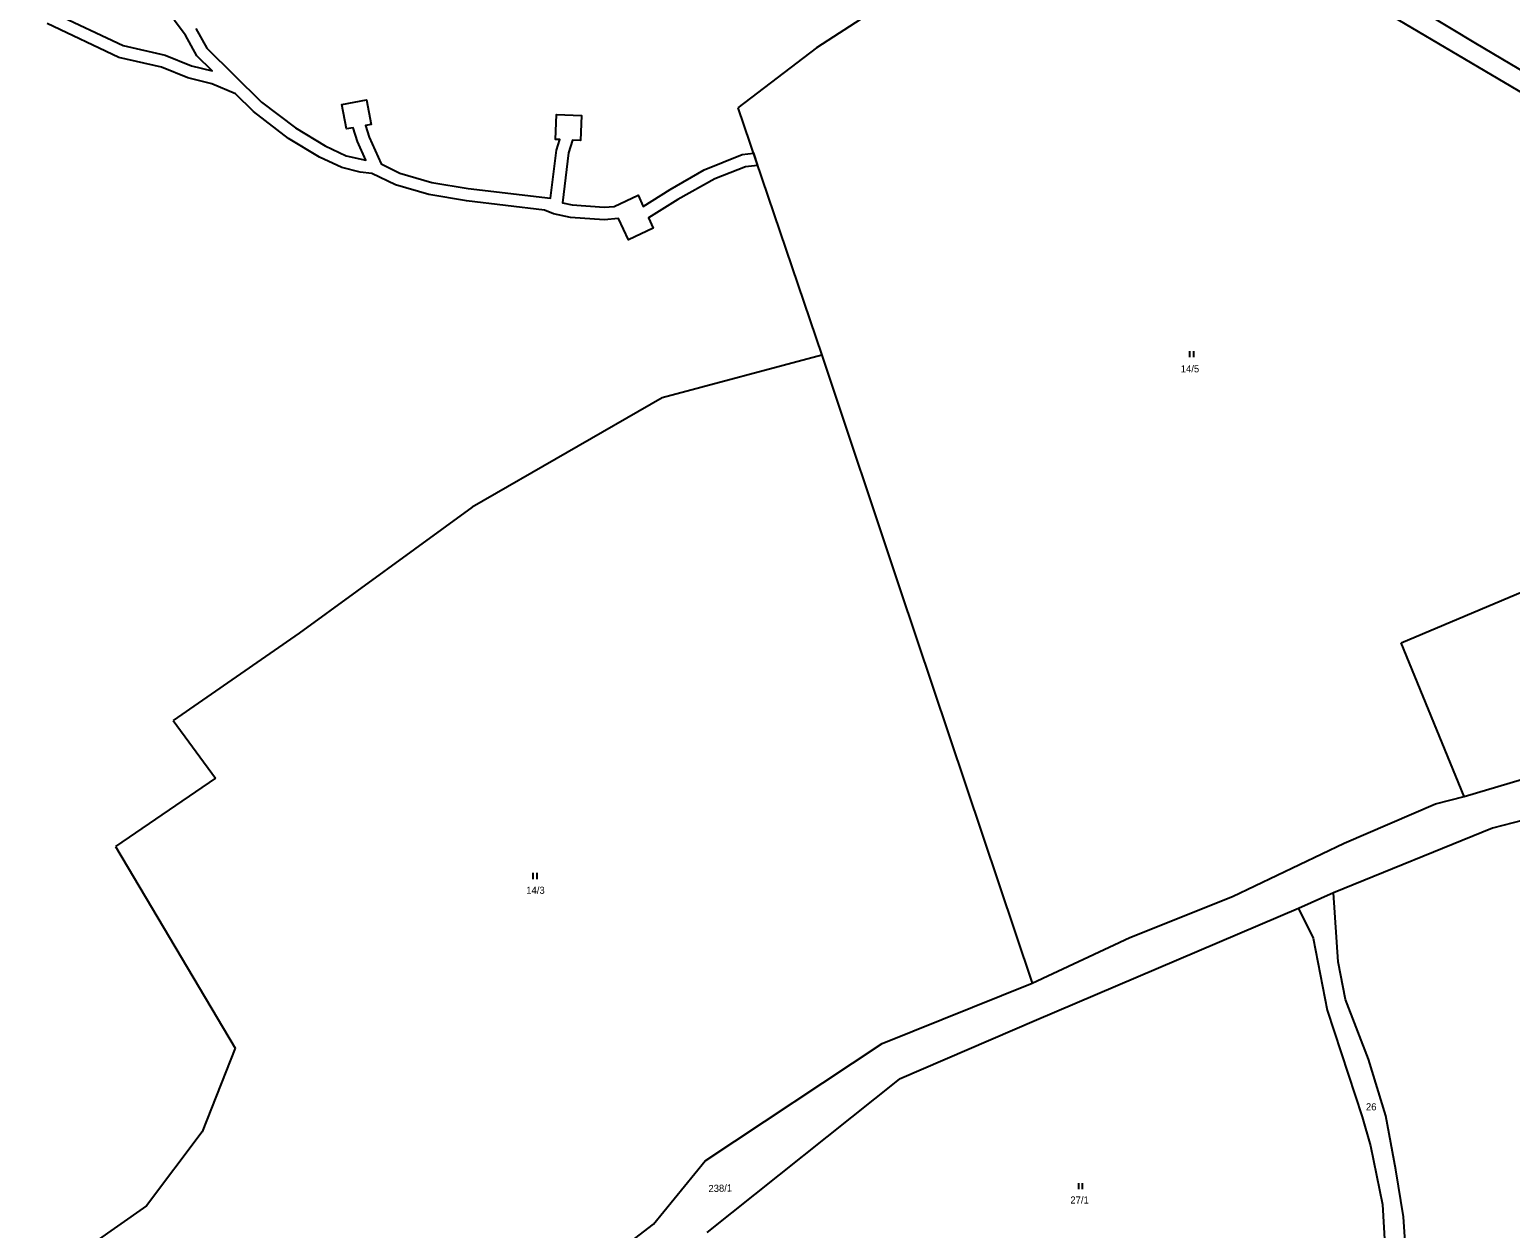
# Model space of a CAD drawing. Extents: x -811039 to -805820, y -1161436 to -1155864.
# Drawn here: x -810524 to -810168.6, y -1160756.4 to -1160468.8 of the extents above; entities that cross this region are included whole.
import ezdxf

# ---------------------------------------------------------------- set-up
doc = ezdxf.new("R2010")
doc.units = 0
for name, color, linetype in [('Default', 7, 'Continuous'), ('Hranice parcel', 7, 'Continuous'), ('Parcelní čísla', 7, 'Continuous'), ('Věcná břemena k části', 7, 'Continuous'), ('Značky kultur', 7, 'Continuous')]:
    doc.layers.add(name, color=color, linetype=linetype)

# ---------------------------------------------------------------- blocks, each defined once
blk = doc.blocks.new('306')
at = {"layer": 'Default'}
for p, q in [((-0.5, 1.5), (-0.5, 0)), ((0.5, 0), (0.5, 1.5))]:
    blk.add_line(p, q, dxfattribs=at)

msp = doc.modelspace()

# ---------------------------------------------------------------- linework, layer by layer
at = {"layer": 'Hranice parcel'}
for p, q in [((-810269.19, -1160416.44), (-810176.95, -1160472.03)), ((-810271.14, -1160421.57), (-810121.75, -1160510.04)), ((-810323.16, -1160465.39), (-810335.15, -1160473.2)), ((-810335.15, -1160473.2), (-810353.97, -1160487.55)), ((-810176.95, -1160472.03), (-810119.8, -1160505.99)), ((-810353.97, -1160487.55), (-810333.83, -1160546.92)), ((-810333.83, -1160546.92), (-810372.15, -1160557.14)), ((-810333.83, -1160546.92), (-810315.21, -1160602.74)), ((-810372.15, -1160557.14), (-810417.74, -1160583.35)), ((-810417.74, -1160583.35), (-810459.3, -1160613.56)), ((-810194.78, -1160615.88), (-810151.5, -1160597.61)), ((-810315.21, -1160602.74), (-810283.33, -1160697.52)), ((-810459.3, -1160613.56), (-810489.53, -1160634.52)), ((-810179.68, -1160652.75), (-810194.78, -1160615.88)), ((-810489.53, -1160634.52), (-810479.35, -1160648.33)), ((-810093.44, -1160639.73), (-810172.86, -1160660.38)), ((-810179.68, -1160652.75), (-810160.58, -1160647.09)), ((-810479.35, -1160648.33), (-810503.37, -1160664.79)), ((-810208.52, -1160663.94), (-810186.6, -1160654.54)), ((-810186.6, -1160654.54), (-810179.68, -1160652.75)), ((-810172.86, -1160660.38), (-810211.06, -1160675.9)), ((-810503.37, -1160664.79), (-810474.66, -1160713.13)), ((-810235.32, -1160676.73), (-810208.52, -1160663.94)), ((-810259.89, -1160686.62), (-810235.32, -1160676.73)), ((-810211.06, -1160675.9), (-810219.42, -1160679.63)), ((-810209.89, -1160692.44), (-810211.06, -1160675.9)), ((-810219.42, -1160679.63), (-810282.35, -1160706.39)), ((-810219.42, -1160679.63), (-810215.96, -1160686.74)), ((-810283.33, -1160697.52), (-810259.89, -1160686.62)), ((-810215.96, -1160686.74), (-810212.53, -1160703.99)), ((-810208.19, -1160701.46), (-810209.89, -1160692.44)), ((-810319.37, -1160712.03), (-810283.33, -1160697.52)), ((-810202.65, -1160715.73), (-810208.19, -1160701.46)), ((-810212.53, -1160703.99), (-810204.21, -1160729.61)), ((-810282.35, -1160706.39), (-810315.18, -1160720.58)), ((-810361.85, -1160740.15), (-810319.37, -1160712.03)), ((-810474.66, -1160713.13), (-810482.58, -1160733.22)), ((-810198.53, -1160729.37), (-810202.65, -1160715.73)), ((-810361.37, -1160757.38), (-810315.18, -1160720.58)), ((-810204.21, -1160729.61), (-810202.14, -1160736.58)), ((-810196.12, -1160742.31), (-810198.53, -1160729.37)), ((-810482.58, -1160733.22), (-810495.95, -1160750.93)), ((-810202.14, -1160736.58), (-810199.32, -1160750.66)), ((-810374.25, -1160755.33), (-810361.85, -1160740.15)), ((-810194.28, -1160753.55), (-810196.12, -1160742.31)), ((-810495.95, -1160750.93), (-810523.97, -1160770.58)), ((-810199.32, -1160750.66), (-810197.13, -1160787.69)), ((-810192.37, -1160781.09), (-810194.28, -1160753.55)), ((-810383.89, -1160762.81), (-810374.25, -1160755.33))]:
    msp.add_line(p, q, dxfattribs=at)
at = {"layer": 'Věcná břemena k části'}
for points in [[(-810518.54, -1160464.64), (-810501.53, -1160472.65), (-810491.43, -1160474.96), (-810485.1, -1160477.48), (-810480.15, -1160478.7), (-810483.82, -1160475.09), (-810486.58, -1160470.17), (-810489.25, -1160466.5)], [(-810484.05, -1160468.55), (-810481.41, -1160473.25), (-810468.29, -1160486.2), (-810460.13, -1160492.4), (-810453.05, -1160496.66), (-810448.01, -1160499.05), (-810443.32, -1160500.12), (-810445.29, -1160495.64), (-810446.36, -1160492.35), (-810447.9, -1160492.64), (-810449.01, -1160486.74), (-810443.11, -1160485.63), (-810442, -1160491.53), (-810443.39, -1160491.79), (-810442.48, -1160494.57), (-810439.64, -1160501.03), (-810435.09, -1160503.22), (-810427.47, -1160505.44), (-810418.71, -1160506.88), (-810398.98, -1160509.23), (-810397.56, -1160497.69), (-810396.76, -1160495.19), (-810397.78, -1160495.15), (-810397.5, -1160489.15), (-810391.51, -1160489.43), (-810391.79, -1160495.42), (-810393.66, -1160495.34), (-810394.62, -1160498.34), (-810396.1, -1160510.39), (-810393.74, -1160510.87), (-810386.08, -1160511.42), (-810383.71, -1160511.2), (-810377.93, -1160508.55), (-810376.73, -1160511.2), (-810370.23, -1160507.17), (-810362.09, -1160502.46), (-810352.93, -1160498.78), (-810350.27, -1160498.45), (-810349.28, -1160501.38), (-810352.18, -1160501.71), (-810359.5, -1160504.63), (-810368.43, -1160509.58), (-810375.48, -1160513.94), (-810374.34, -1160516.45), (-810380.21, -1160519.22), (-810382.67, -1160514.12), (-810386.05, -1160514.43), (-810394.15, -1160513.85), (-810398.21, -1160513.02), (-810400.4, -1160512.08), (-810419.13, -1160509.85), (-810428.14, -1160508.37), (-810436.17, -1160506.03), (-810441.86, -1160503.29), (-810444.64, -1160502.99), (-810449.03, -1160501.89), (-810454.37, -1160499.37), (-810461.81, -1160494.89), (-810470.26, -1160488.47), (-810474.57, -1160484.21), (-810480.24, -1160481.77), (-810486.02, -1160480.34), (-810492.32, -1160477.84), (-810502.52, -1160475.5), (-810519.79, -1160467.37)]]:
    msp.add_lwpolyline(points, dxfattribs=at)

# ---------------------------------------------------------------- block references
at = {"layer": 'Značky kultur'}
for p in [(-810245.09, -1160547.4), (-810402.69, -1160672.56), (-810271.78, -1160746.98)]:
    msp.add_blockref('306', p, dxfattribs=at)

# ---------------------------------------------------------------- texts
at = {"layer": 'Parcelní čísla'}
for s, p in [('14/5', (-810247.71, -1160551.01)), ('14/3', (-810404.78, -1160676.1)), ('26', (-810203.26, -1160728.04)), ('27/1', (-810274.2, -1160750.4))]:
    msp.add_text(s, height=1.7, dxfattribs=at).set_placement(p)
msp.add_text('238/1', height=1.7, rotation=1.547, dxfattribs=at).set_placement((-810361.04, -1160747.65))

doc.saveas('drawing.dxf')
